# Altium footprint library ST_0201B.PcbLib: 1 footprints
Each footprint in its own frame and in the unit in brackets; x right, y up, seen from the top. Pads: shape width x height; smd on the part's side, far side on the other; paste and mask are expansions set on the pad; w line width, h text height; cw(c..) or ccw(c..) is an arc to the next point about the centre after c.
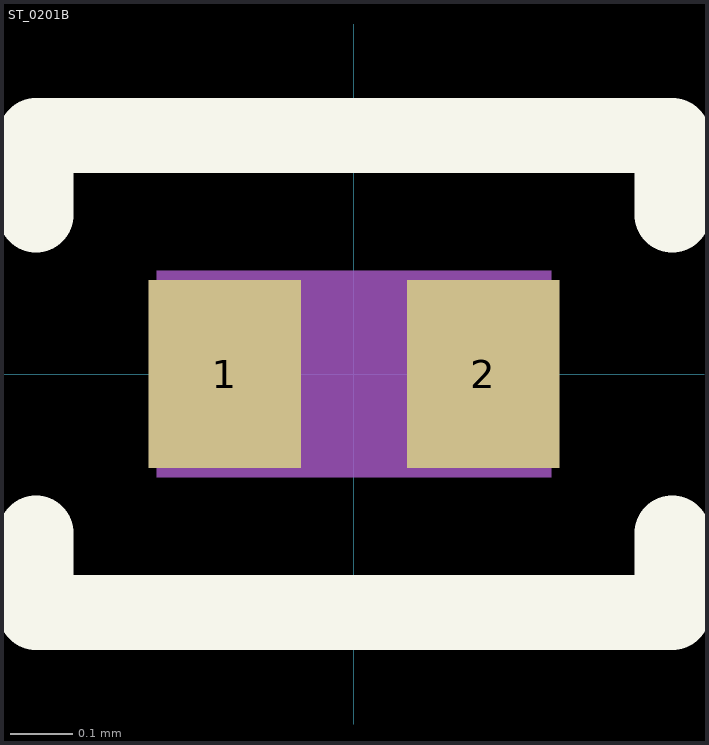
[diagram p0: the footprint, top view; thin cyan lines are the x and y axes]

## ST_0201B [mm]
pads (2):
  rect 0.243x0.3 smd paste-20 mask+0.015: 1(-0.206,0) 2(0.207,0)
Top Overlay:
  lines w0.12: -0.508,-0.254 -0.508,-0.381 0.508,-0.381 0.508,-0.254 ; -0.508,0.254 -0.508,0.381 0.508,0.381 0.508,0.254
Top Paste:
  rectangle: -0.322,-0.142 -0.092,0.143
  rectangle: 0.091,-0.142 0.321,0.143
  region: -0.321,0.269
Mechanical 1:
  rectangle: -0.315,-0.165 0.315,0.165
3D body: height 0.32, standoff 0, extent -0.315,-0.165 0.315,0.165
